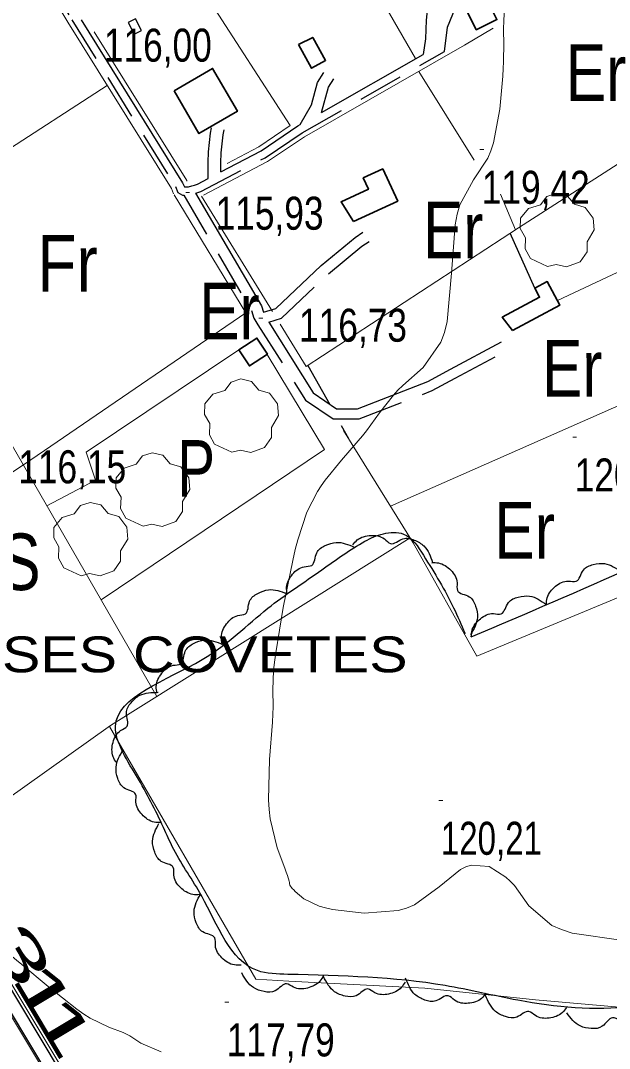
# Model space of a CAD drawing. Extents: x 487425 to 492029, y 4383576 to 4386788.
# Drawn here: x 490540.5 to 490696.7, y 4385746 to 4386018.5 of the extents above; entities that cross this region are included whole.
import ezdxf
from ezdxf.enums import TextEntityAlignment as Align

# ---------------------------------------------------------------- set-up
doc = ezdxf.new("R2010")
doc.units = 0
doc.header["$LTSCALE"] = 4
doc.linetypes.add('LONG_DASHED', pattern=[7.5, 6, -1.5])
doc.linetypes.add('MEDIUM_DASHED', pattern=[4.5, 3, -1.5])
for name, color, linetype, lineweight in [('21', 7, 'Continuous', 25), ('25', 7, 'LONG_DASHED', 25), ('27', 7, 'Continuous', 25), ('29', 7, 'Continuous', 13), ('36', 7, 'Continuous', 25), ('38', 7, 'Continuous', 25), ('47', 7, 'Continuous', 35), ('51', 7, 'Continuous', 13), ('7', 7, 'Continuous', 13), ('9', 7, 'Continuous', 13)]:
    doc.layers.add(name, color=color, linetype=linetype, lineweight=lineweight)
doc.layers.add('31', color=7, linetype='Continuous')
doc.layers.add('5', color=7, linetype='Continuous')

msp = doc.modelspace()

# ---------------------------------------------------------------- linework, layer by layer
at = {"layer": '21'}
msp.add_lwpolyline([(490569.04, 4386018.01), (490570.63, 4386014.86), (490572.55, 4386015.83), (490570.96, 4386018.98)], close=True, dxfattribs=at)
at = {"layer": '25'}
for p, q in [((490676.89, 4385947.55), (490670.4, 4385962.12)), ((490616.73, 4385927.08), (490622.49, 4385916.72)), ((490627.53, 4385907.63), (490625.62, 4385911.08))]:
    msp.add_line(p, q, dxfattribs=at)
at = {"layer": '27'}
for points in [[(490660.05, 4385855.1), (490703.37, 4385873.87), (490750.22, 4385894.5), (490792.49, 4385911.99), (490818.24, 4385924.43), (490830.85, 4385929.34), (490836.56, 4385931.8), (490854.72, 4385936.99), (490859.88, 4385933.16), (490871.16, 4385919.1), (490876.17, 4385912.11), (490877.21, 4385910.46), (490879.3, 4385906.33), (490885.89, 4385880.82), (490884.04, 4385864.03), (490878.8, 4385841.4), (490874.56, 4385829.04), (490861.23, 4385808.46), (490842.67, 4385793.59), (490831.78, 4385788.45), (490814.21, 4385779.96), (490786.75, 4385775.47), (490748.41, 4385766.59), (490719, 4385760.68), (490702.72, 4385757.2), (490672.43, 4385758.79), (490653.1, 4385762.68), (490611.42, 4385765.65), (490603.32, 4385766.65), (490588.54, 4385786.41), (490581.15, 4385798.73), (490578.77, 4385803.76), (490571.76, 4385817.36), (490565.66, 4385831.4), (490588.65, 4385849.1), (490606.09, 4385862.69), (490620.44, 4385872.92), (490631.86, 4385880.46), (490636.74, 4385882.47), (490642.06, 4385882.38), (490647.37, 4385876.74), (490655.35, 4385862.84), (490658.4, 4385856.01)], [(490611.21, 4385866.49), (490611.07, 4385868.26), (490612.64, 4385871.71), (490615.73, 4385873.73), (490617.75, 4385874.08), (490619.06, 4385877.39), (490621.32, 4385879.33), (490624.23, 4385880.17), (490629.02, 4385878.89)], [(490628.61, 4385879.5), (490629.82, 4385880.81), (490633.42, 4385882), (490637, 4385881.1), (490638.63, 4385879.85), (490641.94, 4385881.13), (490644.91, 4385880.78), (490647.49, 4385879.21), (490649.8, 4385874.82)], [(490649.6, 4385874.79), (490651.37, 4385874.72), (490654.63, 4385872.77), (490656.28, 4385869.46), (490656.39, 4385867.41), (490659.53, 4385865.74), (490661.2, 4385863.27), (490661.69, 4385860.28), (490659.87, 4385855.67)], [(490679.97, 4385863.7), (490680.19, 4385865.47), (490682.4, 4385868.54), (490685.83, 4385869.91), (490687.89, 4385869.86), (490689.81, 4385872.84), (490692.42, 4385874.3), (490695.43, 4385874.54), (490699.88, 4385872.34)], [(490593.99, 4385853.29), (490593.76, 4385855.05), (490595.14, 4385858.58), (490598.12, 4385860.76), (490600.13, 4385861.21), (490601.26, 4385864.58), (490603.42, 4385866.64), (490606.28, 4385867.62), (490611.13, 4385866.59)], [(490660.05, 4385855.1), (490660.27, 4385856.86), (490662.49, 4385859.94), (490665.92, 4385861.3), (490667.98, 4385861.24), (490669.91, 4385864.22), (490672.52, 4385865.67), (490675.53, 4385865.91), (490679.97, 4385863.7)], [(490576.67, 4385840.21), (490576.49, 4385841.97), (490577.95, 4385845.47), (490580.97, 4385847.58), (490582.99, 4385847.99), (490584.19, 4385851.34), (490586.39, 4385853.35), (490589.27, 4385854.27), (490594.1, 4385853.14)], [(490565.88, 4385821.8), (490565.03, 4385823.36), (490565.04, 4385827.16), (490567.02, 4385830.26), (490568.73, 4385831.41), (490568.55, 4385834.97), (490569.82, 4385837.67), (490572.12, 4385839.63), (490577.02, 4385840.43)], [(490577.7, 4385805.91), (490575.93, 4385806.01), (490572.71, 4385808.01), (490571.1, 4385811.33), (490571.02, 4385813.39), (490567.91, 4385815.1), (490566.27, 4385817.6), (490565.82, 4385820.59), (490567.71, 4385825.18)], [(490587.95, 4385786.8), (490586.18, 4385786.83), (490582.88, 4385788.7), (490581.14, 4385791.96), (490580.98, 4385794), (490577.8, 4385795.6), (490576.07, 4385798.03), (490575.5, 4385801), (490577.21, 4385805.66)], [(490598.99, 4385768.12), (490597.21, 4385768.15), (490593.91, 4385770.01), (490592.18, 4385773.27), (490592.01, 4385775.32), (490588.83, 4385776.91), (490587.1, 4385779.34), (490586.53, 4385782.31), (490588.23, 4385786.97)], [(490620.85, 4385765.36), (490619.9, 4385763.86), (490616.59, 4385762.02), (490612.9, 4385762.24), (490611.07, 4385763.17), (490608.05, 4385761.29), (490605.07, 4385761.09), (490602.24, 4385762.15), (490599.16, 4385766.04)], [(490642.49, 4385763.63), (490641.49, 4385762.16), (490638.11, 4385760.44), (490634.44, 4385760.79), (490632.64, 4385761.78), (490629.56, 4385760), (490626.58, 4385759.9), (490623.78, 4385761.06), (490620.84, 4385765.05)], [(490663.96, 4385760.63), (490662.79, 4385759.29), (490659.22, 4385757.99), (490655.62, 4385758.78), (490653.95, 4385759.98), (490650.68, 4385758.6), (490647.7, 4385758.86), (490645.08, 4385760.35), (490642.64, 4385764.67)], [(490685.32, 4385756.89), (490684.21, 4385755.51), (490680.7, 4385754.06), (490677.07, 4385754.71), (490675.35, 4385755.84), (490672.14, 4385754.33), (490669.15, 4385754.46), (490666.47, 4385755.85), (490663.85, 4385760.06)], [(490706.96, 4385757.64), (490706.22, 4385756.02), (490703.17, 4385753.76), (490699.49, 4385753.49), (490697.55, 4385754.17), (490694.81, 4385751.9), (490691.88, 4385751.3), (490688.94, 4385751.98), (490685.37, 4385755.43)]]:
    msp.add_spline(points, degree=3, dxfattribs=at)
at = {"layer": '29'}
for points in [[(490680.27, 4385953.29), (490675.73, 4385955.41), (490674.32, 4385957.95), (490674.42, 4385960.93), (490673.05, 4385963.34), (490673.09, 4385966.09), (490675.25, 4385968.69), (490678.44, 4385969.69), (490680.09, 4385971.88), (490682.66, 4385972.71), (490685.52, 4385972.06), (490687.47, 4385969.79), (490690.28, 4385968.97), (490692.41, 4385966.12), (490692.65, 4385962.99), (490690.77, 4385959.84), (490690.77, 4385957.16), (490688.95, 4385954.55), (490685.33, 4385953.21), (490682.56, 4385953.84)], [(490596.52, 4385904.06), (490591.98, 4385906.18), (490590.57, 4385908.72), (490590.67, 4385911.7), (490589.3, 4385914.11), (490589.34, 4385916.86), (490591.5, 4385919.46), (490594.69, 4385920.46), (490596.34, 4385922.65), (490598.91, 4385923.48), (490601.77, 4385922.83), (490603.72, 4385920.56), (490606.53, 4385919.74), (490608.66, 4385916.89), (490608.9, 4385913.76), (490607.02, 4385910.61), (490607.02, 4385907.93), (490605.2, 4385905.32), (490601.58, 4385903.98), (490598.81, 4385904.61)], [(490572.99, 4385884.48), (490568.45, 4385886.6), (490567.04, 4385889.14), (490567.14, 4385892.12), (490565.77, 4385894.53), (490565.81, 4385897.28), (490567.97, 4385899.88), (490571.16, 4385900.88), (490572.81, 4385903.07), (490575.38, 4385903.9), (490578.24, 4385903.25), (490580.19, 4385900.98), (490583, 4385900.16), (490585.13, 4385897.31), (490585.37, 4385894.18), (490583.49, 4385891.03), (490583.49, 4385888.35), (490581.67, 4385885.74), (490578.05, 4385884.4), (490575.28, 4385885.03)], [(490556.53, 4385871.34), (490551.99, 4385873.46), (490550.58, 4385876), (490550.68, 4385878.98), (490549.31, 4385881.39), (490549.35, 4385884.14), (490551.51, 4385886.74), (490554.7, 4385887.74), (490556.35, 4385889.93), (490558.92, 4385890.76), (490561.78, 4385890.11), (490563.73, 4385887.84), (490566.54, 4385887.02), (490568.67, 4385884.17), (490568.91, 4385881.04), (490567.03, 4385877.89), (490567.03, 4385875.21), (490565.21, 4385872.6), (490561.59, 4385871.26), (490558.82, 4385871.89)]]:
    msp.add_lwpolyline(points, close=True, dxfattribs=at)
at = {"layer": '36'}
for points in [[(490584.4, 4385683.64), (490562.69, 4385720.59), (490534.26, 4385767.83), (490517.93, 4385796.29), (490467.18, 4385881.11), (490425.84, 4385950.51), (490355.77, 4386066.34), (490309.21, 4386142.93), (490300.99, 4386157.43), (490300.09, 4386160.55), (490300.1, 4386163.15), (490300.67, 4386167.43), (490302.04, 4386171.69), (490307.23, 4386176.04), (490333.33, 4386192.92)], [(490515.08, 4385794.63), (490531.42, 4385766.16), (490559.85, 4385718.9), (490581.56, 4385681.97)]]:
    msp.add_lwpolyline(points, dxfattribs=at)
at = {"layer": '38'}
msp.add_line((490620.31, 4385994.14), (490647.3, 4386009.54), dxfattribs=at)
at = {"layer": '38', "linetype": 'MEDIUM_DASHED'}
for points in [[(490505.07, 4386099.62), (490528.57, 4386061.18), (490554.09, 4386018.66), (490581.57, 4385974.5), (490582.24, 4385972.95), (490583.46, 4385972.21), (490583.77, 4385972.22)], [(490586.87, 4385972.7), (490587.27, 4385972.83), (490588.3, 4385973.18), (490605.38, 4385982.14), (490615.18, 4385988.73), (490652.95, 4386010.31)], [(490620.31, 4385994.14), (490622.2, 4386000.83), (490623.57, 4386003.04)], [(490590.25, 4385976.62), (490590.26, 4385979.19), (490590.27, 4385980.85), (490590.35, 4385983.68), (490590.9, 4385988.62), (490591.13, 4385990.08)], [(490583.77, 4385972.22), (490601.74, 4385941.63), (490602.4, 4385939.6), (490603.44, 4385937.85)], [(490606.39, 4385938.54), (490609.71, 4385939.56), (490622.16, 4385951.4), (490631.03, 4385958.66), (490632.93, 4385959.97)], [(490603.44, 4385937.85), (490616.11, 4385917.91), (490623.44, 4385912.91), (490630.35, 4385912.89), (490649.66, 4385920.39), (490655.82, 4385923.71), (490669.33, 4385930.94)]]:
    msp.add_lwpolyline(points, dxfattribs=at)
at = {"layer": '38'}
for points in [[(490648.12, 4386049.49), (490643.76, 4386047.18), (490644.8, 4386044.18), (490650.62, 4386035.01), (490650.54, 4386032.31), (490649.33, 4386029.24), (490648.72, 4386024.52), (490648.1, 4386018.6), (490647.93, 4386013.65), (490647.3, 4386009.54)], [(490652.95, 4386010.31), (490653.79, 4386016.78), (490655.15, 4386020.23), (490659.08, 4386031.31), (490659.54, 4386034.08)], [(490556.58, 4386018.73), (490583.48, 4385975.5), (490583.94, 4385974.43), (490584.01, 4385974.39), (490585.05, 4385974.45), (490585.95, 4385974.66), (490586.6, 4385974.87), (490587.45, 4385975.16), (490590.25, 4385976.62)], [(490614.7, 4385990.94), (490617.63, 4385996.18), (490619.3, 4386002.11), (490620.91, 4386004.7)], [(490593.65, 4385978.41), (490604.28, 4385983.99), (490614.04, 4385990.56), (490614.7, 4385990.94)], [(490593.65, 4385978.41), (490593.65, 4385979.17), (490593.66, 4385980.79), (490593.74, 4385983.44), (490594.26, 4385988.16), (490594.48, 4385989.54)], [(490586.87, 4385972.7), (490604.42, 4385942.84), (490604.96, 4385941.17)], [(490604.96, 4385941.17), (490608.19, 4385942.15), (490620.23, 4385953.59), (490629.27, 4385960.99), (490631.28, 4385962.37)], [(490606.39, 4385938.54), (490618.07, 4385919.79), (490624.27, 4385915.58), (490629.85, 4385915.56), (490648.54, 4385922.81), (490654.56, 4385926.06), (490668.08, 4385933.29)]]:
    msp.add_lwpolyline(points, dxfattribs=at)
at = {"layer": '47'}
for points in [[(490664.31, 4386023.95), (490666.85, 4386018.77), (490661.36, 4386016.08), (490658.82, 4386021.27)], [(490614.19, 4386012.18), (490617.69, 4386005.87), (490621.4, 4386007.94), (490617.98, 4386014.04)], [(490581.24, 4385999.9), (490587.81, 4385988.55), (490598.01, 4385994.45), (490591.44, 4386005.8)], [(490628.82, 4385965.19), (490640.53, 4385970.63), (490636.55, 4385979.17), (490631.39, 4385976.77), (490632.78, 4385973.77), (490625.53, 4385970.42)], [(490671.02, 4385936.35), (490683.56, 4385943.06), (490680.2, 4385949.32), (490676.89, 4385947.55), (490678.18, 4385945.13), (490668.28, 4385939.86)], [(490598.42, 4385931.25), (490603.2, 4385934.34), (490605.99, 4385930.02), (490601.21, 4385926.93)]]:
    msp.add_lwpolyline(points, close=True, dxfattribs=at)
at = {"layer": '51'}
for p, q in [((490589.19, 4386026.05), (490611.98, 4385990.64)), ((490660.81, 4385981.52), (490646.11, 4386005.01)), ((490480.85, 4385947.94), (490563.5, 4386001.27)), ((490588.51, 4385971.98), (490607.28, 4385941.4)), ((490671.78, 4385963.02), (490667.83, 4385972.5))]:
    msp.add_line(p, q, dxfattribs=at)
for points in [[(490505.35, 4386096.84), (490527.53, 4386060.55), (490553.06, 4386018.03), (490580.49, 4385973.94), (490581.08, 4385972.58)], [(490669.43, 4386086.15), (490619.93, 4386052.27), (490645.29, 4386008.41)], [(490560.01, 4386015.53), (490584.56, 4385976.06), (490584.61, 4385975.95)], [(490665.86, 4386016.44), (490658.25, 4386011.94), (490615.82, 4385987.7), (490606, 4385981.1), (490589.02, 4385972.19)], [(490479.17, 4386002.13), (490504.95, 4385963.47), (490541.27, 4385900.68), (490576.6, 4385839.29)], [(490728.95, 4385999.68), (490672.6, 4385963.56), (490616.25, 4385926.77), (490609.38, 4385937.98)], [(490595.27, 4385980.64), (490603.66, 4385985.04), (490611.98, 4385990.64)], [(490480.34, 4385860.67), (490541.57, 4385900.9), (490600.25, 4385940.99), (490581.2, 4385972.33)], [(490731.96, 4385929.72), (490716.3, 4385959.91), (490682.93, 4385944.26)], [(490598.42, 4385931.25), (490557.93, 4385904.08), (490560.38, 4385896.64), (490547.5, 4385889.87)], [(490605.94, 4385929.99), (490621.14, 4385904.78), (490561.86, 4385864.91)], [(490638.63, 4385889.79), (490731.44, 4385930.69), (490753.99, 4385888.38)], [(490778.5, 4385898.54), (490661.54, 4385850), (490644.68, 4385880.04), (490626.18, 4385909.79)], [(490585.08, 4385684.04), (490563.37, 4385720.99), (490534.94, 4385768.23), (490518.61, 4385796.69), (490467.86, 4385881.52), (490462.62, 4385890.32)], [(490643.84, 4385881.41), (490564.38, 4385831.63), (490519.45, 4385799.74)], [(490813.86, 4385787.68), (490803.12, 4385784.04), (490802.04, 4385774.07), (490785.24, 4385771.95), (490734.22, 4385761.61), (490710.44, 4385755.98), (490677.08, 4385758.93), (490647.7, 4385762.02), (490611.64, 4385763.85), (490602.94, 4385764.4), (490564.05, 4385831.4)], [(490581.24, 4385681.78), (490559.54, 4385718.72), (490531.1, 4385765.97), (490519.59, 4385786.05)]]:
    msp.add_lwpolyline(points, dxfattribs=at)
at = {"layer": '7'}
for p, q in [((490662.34, 4385984.29), (490663.34, 4385984.29)), ((490584.33, 4385972.9), (490585.33, 4385972.9)), ((490603.72, 4385939.63), (490604.72, 4385939.63)), ((490687, 4385908.03), (490688, 4385908.03)), ((490651.47, 4385811.72), (490652.47, 4385811.72)), ((490594.7, 4385758.28), (490595.7, 4385758.28))]:
    msp.add_line(p, q, dxfattribs=at)
at = {"layer": '9'}
for points in [[(490606.26, 4385811.93), (490606.57, 4385822.6), (490607.31, 4385832.52), (490607.42, 4385834.66), (490607.49, 4385836.54), (490607.41, 4385841.12), (490607.62, 4385846.21), (490607.88, 4385848.4), (490608.22, 4385850.93), (490610.19, 4385862.89), (490612.69, 4385875.4), (490613.37, 4385878.27), (490614.04, 4385880.88), (490616.43, 4385888.17), (490619.27, 4385893.7), (490620.23, 4385895.2), (490621.26, 4385896.69), (490625.6, 4385901.97), (490630.08, 4385907.05), (490631.21, 4385908.42), (490632.28, 4385909.78), (490635.74, 4385914.52), (490639.4, 4385919.18), (490640.61, 4385920.48), (490641.9, 4385921.78), (490647.25, 4385926.54), (490652, 4385933.28), (490652.91, 4385935.84), (490653.65, 4385938.7), (490654.83, 4385951.52), (490655.75, 4385964.31), (490656.31, 4385967.15), (490657.01, 4385969.69), (490660.63, 4385976.3), (490664.44, 4385981.99), (490665.25, 4385983.93), (490665.96, 4385986.04), (490667.64, 4385995), (490668.4, 4386003.79), (490668.54, 4386005.79), (490668.64, 4386007.59), (490668.72, 4386012.55), (490668.62, 4386015.64), (490668.61, 4386016.26), (490668.61, 4386016.79), (490668.66, 4386017.88), (490668.79, 4386020.85)], [(490700.34, 4385774.67), (490686.85, 4385776.61), (490683.96, 4385777.52), (490681.44, 4385778.58), (490675.36, 4385783.78), (490671.5, 4385789.18), (490670.37, 4385790.38), (490669.22, 4385791.44), (490664.84, 4385794.22), (490660.04, 4385794.57), (490658.62, 4385794.12), (490657.16, 4385793.42), (490651.57, 4385788.88), (490644.96, 4385784.09), (490642.86, 4385783.23), (490640.63, 4385782.57), (490631.61, 4385781.9), (490623.2, 4385782.88), (490621.36, 4385783.26), (490619.73, 4385783.7), (490615.61, 4385785.69), (490613.38, 4385787.64), (490612.94, 4385788.06), (490612.58, 4385788.42), (490611.94, 4385789.28), (490611.84, 4385789.74), (490611.82, 4385789.86), (490611.8, 4385789.97), (490611.78, 4385790.32), (490611.28, 4385791.88), (490610.97, 4385792.75), (490610.58, 4385793.81), (490608.53, 4385799.23), (490606.68, 4385806.86), (490606.42, 4385809.32), (490606.26, 4385811.93)], [(490535.06, 4385773.13), (490535.01, 4385773.03), (490534.96, 4385772.93), (490534.96, 4385772.9), (490534.95, 4385772.87), (490534.94, 4385772.73), (490535.09, 4385772.54), (490535.19, 4385772.47), (490535.31, 4385772.39), (490535.95, 4385772.07), (490538.26, 4385770.38), (490539.43, 4385769.43), (490540.83, 4385768.28), (490547.83, 4385762.42), (490555.46, 4385756.39), (490557.27, 4385755.13), (490558.94, 4385754.05), (490563.88, 4385751.65), (490567.67, 4385750.25), (490568.62, 4385749.81), (490569.52, 4385749.34), (490572.41, 4385747.45), (490577.75, 4385745.1)]]:
    msp.add_lwpolyline(points, dxfattribs=at)

# ---------------------------------------------------------------- texts
at = {"layer": '31'}
for s, width, p in [('Er', 0.8, (490693.15, 4385997.15)), ('Er', 0.8, (490655.26, 4385955.46)), ('Fr', 0.85, (490552.96, 4385946.61)), ('Er', 0.8, (490595.91, 4385933.98)), ('Er', 0.8, (490686.84, 4385918.82)), ('P', 0.75, (490587.06, 4385892.28)), ('Er', 0.8, (490674.21, 4385875.86)), ('S', 0.8, (490540.45, 4385867.52))]:
    msp.add_text(s, height=15, dxfattribs=dict(at, width=width)).set_placement(p, align=Align.CENTER)
at = {"layer": '5', "width": 1.2}
msp.add_text('SES COVETES', height=9.5, dxfattribs=at).set_placement((490643.16, 4385845.73), align=Align.RIGHT)
at = {"layer": '5', "width": 2}
for s, p in [('3', (490535.92, 4385768.04)), ('1', (490542.01, 4385757.84)), ('1', (490547.29, 4385748.99))]:
    msp.add_text(s, height=10.99, rotation=300.852, dxfattribs=at).set_placement(p, align=Align.CENTER)
at = {"layer": '7'}
for s, width, p in [('116,00', 0.8, (490562.59, 4386007.6)), ('119,42', 0.8, (490662.84, 4385969.92)), ('115,93', 0.8, (490592.24, 4385963.05)), ('116,73', 0.8, (490614.36, 4385933.36)), ('116,15', 0.8, (490539.88, 4385895.83)), ('120,62', 0.8, (490687.5, 4385893.66)), ('120,21', 0.75, (490651.97, 4385797.35)), ('117,79', 0.8, (490595.2, 4385743.91))]:
    msp.add_text(s, height=8.75, dxfattribs=dict(at, width=width)).set_placement(p)

doc.saveas('drawing.dxf')
